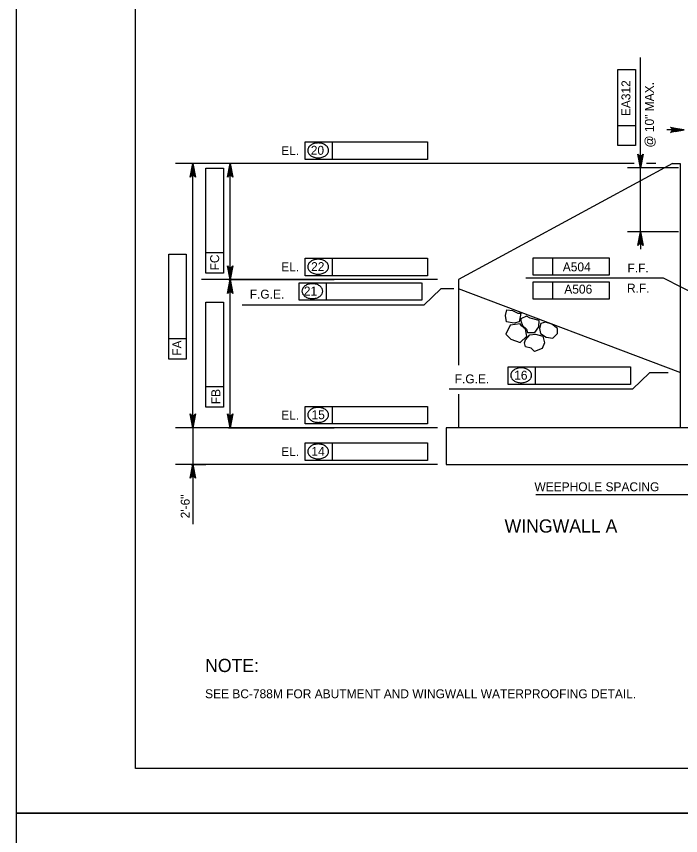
# Model space of a CAD drawing. Extents: x 638340 to 640242, y 295465 to 298435.
# Drawn here: x 638435.5 to 638658.4, y 297834 to 298109 of the extents above; entities that cross this region are included whole.
import ezdxf

# ---------------------------------------------------------------- set-up
doc = ezdxf.new("R2010")
doc.units = 0
for name, color, linetype in [('1', 7, 'Continuous'), ('2', 7, 'Continuous'), ('3', 7, 'Continuous'), ('4', 7, 'Continuous'), ('Level 10', 7, 'Continuous'), ('Level 3', 7, 'Continuous'), ('Level 4', 7, 'Continuous'), ('PLT-BNDY', 7, 'Continuous')]:
    doc.layers.add(name, color=color, linetype=linetype)

# ---------------------------------------------------------------- blocks, each defined once
blk = doc.blocks.new('ROCK')
at = {"layer": '4'}
for points in [[(2.36725, 1.088), (2.2065, 0.82625), (2.378625, 0.506625), (2.66975, 0.3095), (3.128875, 0.403375), (3.48475, 0.6775), (3.4915, 1.123375), (3.25625, 1.36725), (2.783625, 1.308375)], [(1.10175, -0.02725), (1.4015, -0.159125), (1.78825, -0.148875), (1.980875, -0.266), (2.343375, 0.09475), (2.27875, 0.5505), (1.969375, 0.883), (1.4225, 0.553625), (1.152875, 0.479), (1.0105, 0.082)], [(0.74675, 0.359875), (0.882, 0.16), (1.072875, -0.144), (0.892, -0.457375), (0.448125, -0.758625), (0.1, -0.49325), (-0.095, -0.146375), (0.202875, 0.1025), (0.579125, 0.219875)], [(2.231375, -0.71725), (2.2025, -0.266375), (2.45475, 0.037125), (2.9085, 0.28875), (3.2995, 0.047625), (3.46875, -0.344), (3.231625, -0.855), (2.92, -0.860375), (2.5765, -1.054625), (2.340375, -0.904375)], [(1.2085, -0.192875), (0.778375, -0.737625), (1.008375, -1.391375), (1.48725, -1.396875), (2.09825, -1.106625), (2.133375, -0.486375), (1.723125, -0.203375), (1.37425, -0.239875)]]:
    blk.add_lwpolyline(points, close=True, dxfattribs=at)
blk = doc.blocks.new('V')
at = {"layer": '1'}
blk.add_line((0, 0), (0, 0), dxfattribs=at)

msp = doc.modelspace()

# ---------------------------------------------------------------- linework, layer by layer
at = {"layer": '2'}
for p, q in [((638475.46, 297856.46), (638475.46, 298420.46)), ((639261.46, 297856.46), (638475.46, 297856.46))]:
    msp.add_line(p, q, dxfattribs=at)
at = {"layer": 'Level 10'}
for p, q in [((638655.6, 298059.67), (638583.82, 298020.62)), ((638655.6, 298059.67), (638658.26, 298059.67)), ((638658.26, 298059.67), (638658.26, 297970.89)), ((638583.82, 298020.62), (638583.82, 297991.94)), ((638658.48, 297989.3), (638583.82, 298017.55)), ((638583.82, 297982.19), (638583.82, 297970.89)), ((638579.73, 297970.89), (638579.73, 297958.61)), ((638740.63, 297970.89), (638579.73, 297970.89)), ((638579.73, 297958.61), (638960.22, 297958.61))]:
    msp.add_line(p, q, dxfattribs=at)
at = {"layer": 'Level 3'}
for p, q in [((638644.93, 298064.03), (638644.93, 298095.19)), ((638637.34, 298065.7), (638637.34, 298091.19)), ((638637.34, 298091.19), (638643.23, 298091.19)), ((638643.23, 298091.19), (638643.23, 298065.7)), ((638643.23, 298072.28), (638637.34, 298072.28)), ((638659.61, 298070.9), (638653.73, 298070.9)), ((638532.35, 298066.84), (638541.5, 298066.84)), ((638532.35, 298060.95), (638532.35, 298066.84)), ((638541.5, 298060.95), (638541.5, 298066.84)), ((638541.5, 298066.84), (638573.48, 298066.84)), ((638573.48, 298066.84), (638573.48, 298060.95)), ((638643.23, 298065.7), (638637.34, 298065.7)), ((638644.93, 298061.08), (638644.93, 298064.03)), ((638573.48, 298060.95), (638532.35, 298060.95)), ((638642.74, 298059.67), (638488.89, 298059.67)), ((638494.99, 298059.67), (638490.23, 298059.67)), ((638502.18, 298059.67), (638490.23, 298059.67)), ((638494.65, 297970.89), (638494.65, 298059.67)), ((638542.23, 298059.67), (638502.76, 298059.67)), ((638507.18, 298020.62), (638507.18, 298059.67)), ((638657.72, 298058.13), (638640.51, 298058.13)), ((638644.93, 298036.7), (638644.93, 298058.13)), ((638650.09, 298059.67), (638646.98, 298059.67)), ((638499.08, 298058.05), (638504.98, 298058.05)), ((638499.08, 298029.65), (638499.08, 298058.05)), ((638504.98, 298058.05), (638504.98, 298022.82)), ((638657.72, 298036.7), (638640.51, 298036.7)), ((638644.93, 298033.75), (638644.93, 298030.81)), ((638486.6, 298029.17), (638492.49, 298029.17)), ((638486.6, 298000.77), (638486.6, 298029.17)), ((638492.49, 298029.17), (638492.49, 297993.94)), ((638499.08, 298022.82), (638499.08, 298029.65)), ((638504.98, 298029.65), (638499.08, 298029.65)), ((638608.93, 298027.99), (638634.42, 298027.99)), ((638608.93, 298022.09), (638608.93, 298027.99)), ((638615.51, 298022.09), (638615.51, 298027.99)), ((638634.42, 298027.99), (638634.42, 298022.09)), ((638532.35, 298027.79), (638541.5, 298027.79)), ((638532.35, 298021.9), (638532.35, 298027.79)), ((638541.5, 298021.9), (638541.5, 298027.79)), ((638541.5, 298027.79), (638573.48, 298027.79)), ((638573.48, 298027.79), (638573.48, 298021.9)), ((638504.98, 298022.82), (638499.08, 298022.82)), ((638576.74, 298020.62), (638497.59, 298020.62)), ((638542.23, 298020.62), (638502.76, 298020.62)), ((638548.62, 298020.62), (638502.76, 298020.62)), ((638506.6, 298020.62), (638542.05, 298020.62)), ((638507.18, 297970.89), (638507.18, 298020.62)), ((638530.41, 298013.7), (638530.41, 298019.59)), ((638530.41, 298019.59), (638539.58, 298019.59)), ((638573.48, 298021.9), (638532.35, 298021.9)), ((638539.57, 298013.7), (638539.57, 298019.59)), ((638539.57, 298019.59), (638571.37, 298019.59)), ((638571.55, 298019.59), (638571.55, 298013.7)), ((638606.39, 298021.22), (638652.48, 298021.22)), ((638634.42, 298022.09), (638608.93, 298022.09)), ((638608.93, 298014.03), (638608.93, 298019.92)), ((638608.93, 298019.92), (638634.42, 298019.92)), ((638615.51, 298014.03), (638615.51, 298019.92)), ((638634.42, 298019.92), (638634.42, 298014.03)), ((638652.48, 298021.22), (638674.89, 298009.76)), ((638577.85, 298017.55), (638572.15, 298012.05)), ((638499.08, 298013.01), (638504.98, 298013.01)), ((638499.08, 297984.6), (638499.08, 298013.01)), ((638504.98, 298013.01), (638504.98, 297977.77)), ((638572.15, 298012.05), (638511.24, 298012.05)), ((638571.55, 298013.7), (638530.41, 298013.7)), ((638634.42, 298014.03), (638608.93, 298014.03)), ((638486.6, 297993.94), (638486.6, 298000.77)), ((638492.49, 298000.77), (638486.6, 298000.77)), ((638492.49, 297993.94), (638486.6, 297993.94)), ((638600.48, 297991.35), (638609.64, 297991.35)), ((638600.48, 297985.45), (638600.48, 297991.35)), ((638609.64, 297985.45), (638609.64, 297991.35)), ((638609.64, 297991.35), (638641.61, 297991.35)), ((638641.61, 297991.35), (638641.61, 297985.45)), ((638647.91, 297989.3), (638642.21, 297983.81)), ((638654.16, 297989.3), (638647.91, 297989.3)), ((638499.08, 297977.77), (638499.08, 297984.6)), ((638504.98, 297984.6), (638499.08, 297984.6)), ((638641.61, 297985.45), (638600.48, 297985.45)), ((638642.21, 297983.81), (638580.65, 297983.81)), ((638504.98, 297977.77), (638499.08, 297977.77)), ((638532.35, 297978.06), (638541.5, 297978.06)), ((638532.35, 297972.16), (638532.35, 297978.06)), ((638541.5, 297972.16), (638541.5, 297978.06)), ((638541.5, 297978.06), (638573.48, 297978.06)), ((638573.48, 297978.06), (638573.48, 297972.16)), ((638576.74, 297970.89), (638488.89, 297970.89)), ((638494.99, 297970.89), (638490.23, 297970.89)), ((638502.18, 297970.89), (638490.23, 297970.89)), ((638494.65, 297970.89), (638494.65, 297958.61)), ((638548.62, 297970.89), (638502.76, 297970.89)), ((638506.6, 297970.89), (638542.05, 297970.89)), ((638573.48, 297972.16), (638532.35, 297972.16)), ((638532.35, 297965.78), (638541.5, 297965.78)), ((638532.35, 297959.89), (638532.35, 297965.78)), ((638541.5, 297959.89), (638541.5, 297965.78)), ((638541.5, 297965.78), (638573.48, 297965.78)), ((638573.48, 297965.78), (638573.48, 297959.89)), ((638573.48, 297959.89), (638532.35, 297959.89)), ((638576.74, 297958.61), (638488.89, 297958.61)), ((638494.06, 297958.61), (638499.07, 297958.61)), ((638494.65, 297958.61), (638494.65, 297938.57)), ((638890.47, 297948.39), (638609.81, 297948.39))]:
    msp.add_line(p, q, dxfattribs=at)
for points in [[(638659.61, 298070.9), (638654.96, 298070.03), (638655.32, 298070.28), (638655.5, 298070.59), (638655.56, 298070.9), (638655.5, 298071.21), (638655.32, 298071.53), (638654.96, 298071.77), (638659.61, 298070.9), (638655.32, 298071.53), (638655.5, 298071.21), (638659.61, 298070.9), (638655.56, 298070.9), (638655.5, 298070.59), (638659.61, 298070.9), (638655.32, 298070.28)], [(638644.93, 298058.13), (638644.06, 298062.79), (638644.31, 298062.43), (638644.62, 298062.24), (638644.93, 298062.19), (638645.24, 298062.24), (638645.56, 298062.43), (638645.8, 298062.79), (638644.93, 298058.13), (638645.56, 298062.43), (638645.24, 298062.24), (638644.93, 298058.13), (638644.93, 298062.19), (638644.62, 298062.24), (638644.93, 298058.13), (638644.31, 298062.43)], [(638494.65, 298059.67), (638495.52, 298055.02), (638495.28, 298055.37), (638494.97, 298055.56), (638494.65, 298055.61), (638494.34, 298055.56), (638494.03, 298055.37), (638493.78, 298055.02), (638494.65, 298059.67), (638494.03, 298055.37), (638494.34, 298055.56), (638494.65, 298059.67), (638494.65, 298055.61), (638494.97, 298055.56), (638494.65, 298059.67), (638495.28, 298055.37)], [(638507.18, 298059.67), (638508.05, 298055.02), (638507.8, 298055.37), (638507.49, 298055.56), (638507.18, 298055.61), (638506.87, 298055.56), (638506.55, 298055.37), (638506.31, 298055.02), (638507.18, 298059.67), (638506.55, 298055.37), (638506.87, 298055.56), (638507.18, 298059.67), (638507.18, 298055.61), (638507.49, 298055.56), (638507.18, 298059.67), (638507.8, 298055.37)], [(638644.93, 298036.7), (638645.8, 298032.05), (638645.56, 298032.41), (638645.24, 298032.59), (638644.93, 298032.64), (638644.62, 298032.59), (638644.31, 298032.41), (638644.06, 298032.05), (638644.93, 298036.7), (638644.31, 298032.41), (638644.62, 298032.59), (638644.93, 298036.7), (638644.93, 298032.64), (638645.24, 298032.59), (638644.93, 298036.7), (638645.56, 298032.41)], [(638507.18, 298020.62), (638506.31, 298025.27), (638506.55, 298024.91), (638506.87, 298024.73), (638507.18, 298024.67), (638507.49, 298024.73), (638507.8, 298024.91), (638508.05, 298025.27), (638507.18, 298020.62), (638507.8, 298024.91), (638507.49, 298024.73), (638507.18, 298020.62), (638507.18, 298024.67), (638506.87, 298024.73), (638507.18, 298020.62), (638506.55, 298024.91)], [(638507.18, 298020.62), (638508.05, 298015.97), (638507.8, 298016.32), (638507.49, 298016.51), (638507.18, 298016.56), (638506.87, 298016.51), (638506.55, 298016.32), (638506.31, 298015.97), (638507.18, 298020.62), (638506.55, 298016.32), (638506.87, 298016.51), (638507.18, 298020.62), (638507.18, 298016.56), (638507.49, 298016.51), (638507.18, 298020.62), (638507.8, 298016.32)], [(638494.65, 297970.89), (638493.78, 297975.54), (638494.03, 297975.18), (638494.34, 297974.99), (638494.65, 297974.94), (638494.97, 297974.99), (638495.28, 297975.18), (638495.52, 297975.54), (638494.65, 297970.89), (638495.28, 297975.18), (638494.97, 297974.99), (638494.65, 297970.89), (638494.65, 297974.94), (638494.34, 297974.99), (638494.65, 297970.89), (638494.03, 297975.18)], [(638507.18, 297970.89), (638506.31, 297975.54), (638506.55, 297975.18), (638506.87, 297974.99), (638507.18, 297974.94), (638507.49, 297974.99), (638507.8, 297975.18), (638508.05, 297975.54), (638507.18, 297970.89), (638507.8, 297975.18), (638507.49, 297974.99), (638507.18, 297970.89), (638507.18, 297974.94), (638506.87, 297974.99), (638507.18, 297970.89), (638506.55, 297975.18)], [(638494.65, 297958.61), (638495.52, 297953.96), (638495.28, 297954.31), (638494.97, 297954.5), (638494.65, 297954.55), (638494.34, 297954.5), (638494.03, 297954.31), (638493.78, 297953.96), (638494.65, 297958.61), (638494.03, 297954.31), (638494.34, 297954.5), (638494.65, 297958.61), (638494.65, 297954.55), (638494.97, 297954.5), (638494.65, 297958.61), (638495.28, 297954.31)]]:
    msp.add_lwpolyline(points, dxfattribs=at)
for points in [[(638656.68, 298071.39), (638656.68, 298070.41), (638659.62, 298070.9)], [(638644.44, 298061.08), (638645.42, 298061.08), (638644.93, 298058.13)], [(638494.16, 298056.72), (638495.14, 298056.72), (638494.65, 298059.67)], [(638506.69, 298056.72), (638507.67, 298056.72), (638507.18, 298059.67)], [(638644.44, 298033.75), (638645.42, 298033.75), (638644.93, 298036.7)], [(638506.69, 298023.57), (638507.67, 298023.57), (638507.18, 298020.62)], [(638506.69, 298017.67), (638507.67, 298017.67), (638507.18, 298020.62)], [(638494.16, 297973.83), (638495.14, 297973.83), (638494.65, 297970.89)], [(638506.69, 297973.83), (638507.67, 297973.83), (638507.18, 297970.89)], [(638494.16, 297955.66), (638495.14, 297955.66), (638494.65, 297958.61)]]:
    msp.add_lwpolyline(points, close=True, dxfattribs=at)
for centre, radius, start, end in [((638536.72, 298061.64), 4.86, 90, 106.5358), ((638536.72, 298061.64), 4.86, 73.4642, 90), ((638535.04, 298064), 1.82, 149.9767, 180), ((638535.04, 298064), 1.82, 180, 210.0233), ((638535.85, 298063.54), 2.75, 125.6316, 149.9767), ((638536.37, 298062.8), 3.65, 106.5358, 125.6316), ((638537.06, 298062.8), 3.65, 54.3684, 73.4642), ((638537.59, 298063.54), 2.75, 30.0233, 54.3684), ((638538.39, 298064), 1.82, 0, 30.0233), ((638538.39, 298064), 1.82, 329.9767, 0), ((638535.85, 298064.47), 2.75, 210.0233, 234.3684), ((638536.37, 298065.2), 3.65, 234.3684, 253.4642), ((638536.72, 298066.36), 4.86, 253.4642, 270), ((638536.72, 298066.36), 4.86, 270, 286.5358), ((638537.06, 298065.2), 3.65, 286.5358, 305.6316), ((638537.59, 298064.47), 2.75, 305.6316, 329.9767), ((638535.04, 298024.95), 1.82, 149.9767, 180), ((638535.85, 298024.49), 2.75, 125.6316, 149.9767), ((638536.37, 298023.75), 3.65, 106.5358, 125.6316), ((638536.72, 298022.6), 4.86, 90, 106.5358), ((638536.72, 298022.6), 4.86, 73.4642, 90), ((638537.06, 298023.75), 3.65, 54.3684, 73.4642), ((638537.59, 298024.49), 2.75, 30.0233, 54.3684), ((638538.39, 298024.95), 1.82, 0, 30.0233), ((638535.04, 298024.95), 1.82, 180, 210.0233), ((638535.85, 298025.42), 2.75, 210.0233, 234.3684), ((638536.37, 298026.15), 3.65, 234.3684, 253.4642), ((638536.72, 298027.31), 4.86, 253.4642, 270), ((638536.72, 298027.31), 4.86, 270, 286.5358), ((638537.06, 298026.15), 3.65, 286.5358, 305.6316), ((638537.59, 298025.42), 2.75, 305.6316, 329.9767), ((638538.39, 298024.95), 1.82, 329.9767, 0), ((638533.11, 298016.75), 1.82, 149.9767, 180), ((638533.91, 298016.28), 2.75, 125.6316, 149.9767), ((638534.44, 298015.55), 3.65, 106.5358, 125.6316), ((638534.78, 298014.39), 4.86, 90, 106.5358), ((638534.78, 298014.39), 4.86, 73.4642, 90), ((638535.13, 298015.55), 3.65, 54.3684, 73.4642), ((638535.65, 298016.28), 2.75, 30.0233, 54.3684), ((638536.46, 298016.75), 1.82, 0, 30.0233), ((638533.11, 298016.75), 1.82, 180, 210.0233), ((638533.91, 298017.21), 2.75, 210.0233, 234.3684), ((638534.44, 298017.95), 3.65, 234.3684, 253.4642), ((638534.78, 298019.1), 4.86, 253.4642, 270), ((638534.78, 298019.1), 4.86, 270, 286.5358), ((638535.13, 298017.95), 3.65, 286.5358, 305.6316), ((638535.65, 298017.21), 2.75, 305.6316, 329.9767), ((638536.46, 298016.75), 1.82, 329.9767, 0), ((638603.18, 297988.51), 1.82, 149.9767, 180), ((638603.98, 297988.04), 2.75, 125.6316, 149.9767), ((638604.51, 297987.31), 3.65, 106.5358, 125.6316), ((638604.85, 297986.15), 4.86, 90, 106.5358), ((638604.85, 297986.15), 4.86, 73.4642, 90), ((638605.19, 297987.31), 3.65, 54.3684, 73.4642), ((638605.72, 297988.04), 2.75, 30.0233, 54.3684), ((638606.52, 297988.51), 1.82, 0, 30.0233), ((638603.18, 297988.51), 1.82, 180, 210.0233), ((638603.98, 297988.97), 2.75, 210.0233, 234.3684), ((638604.51, 297989.7), 3.65, 234.3684, 253.4642), ((638605.19, 297989.7), 3.65, 286.5358, 305.6316), ((638605.72, 297988.97), 2.75, 305.6316, 329.9767), ((638606.52, 297988.51), 1.82, 329.9767, 0), ((638604.85, 297990.86), 4.86, 253.4642, 270), ((638604.85, 297990.86), 4.86, 270, 286.5358), ((638535.04, 297975.22), 1.82, 149.9767, 180), ((638535.85, 297974.75), 2.75, 125.6316, 149.9767), ((638536.37, 297974.02), 3.65, 106.5358, 125.6316), ((638536.72, 297972.86), 4.86, 90, 106.5358), ((638536.72, 297972.86), 4.86, 73.4642, 90), ((638537.06, 297974.02), 3.65, 54.3684, 73.4642), ((638537.59, 297974.75), 2.75, 30.0233, 54.3684), ((638538.39, 297975.22), 1.82, 0, 30.0233), ((638535.04, 297975.22), 1.82, 180, 210.0233), ((638535.85, 297975.68), 2.75, 210.0233, 234.3684), ((638536.37, 297976.42), 3.65, 234.3684, 253.4642), ((638536.72, 297977.57), 4.86, 253.4642, 270), ((638536.72, 297977.57), 4.86, 270, 286.5358), ((638537.06, 297976.42), 3.65, 286.5358, 305.6316), ((638537.59, 297975.68), 2.75, 305.6316, 329.9767), ((638538.39, 297975.22), 1.82, 329.9767, 0), ((638535.85, 297962.47), 2.75, 125.6316, 149.9767), ((638536.37, 297961.74), 3.65, 106.5358, 125.6316), ((638536.72, 297960.58), 4.86, 90, 106.5358), ((638536.72, 297960.58), 4.86, 73.4642, 90), ((638537.06, 297961.74), 3.65, 54.3684, 73.4642), ((638537.59, 297962.47), 2.75, 30.0233, 54.3684), ((638535.04, 297962.94), 1.82, 149.9767, 180), ((638535.04, 297962.94), 1.82, 180, 210.0233), ((638535.85, 297963.4), 2.75, 210.0233, 234.3684), ((638537.59, 297963.4), 2.75, 305.6316, 329.9767), ((638538.39, 297962.94), 1.82, 0, 30.0233), ((638538.39, 297962.94), 1.82, 329.9767, 0), ((638536.37, 297964.14), 3.65, 234.3684, 253.4642), ((638536.72, 297965.29), 4.86, 253.4642, 270), ((638536.72, 297965.29), 4.86, 270, 286.5358), ((638537.06, 297964.14), 3.65, 286.5358, 305.6316)]:
    msp.add_arc(centre, radius, start, end, dxfattribs=at)
at = {"layer": 'Level 4'}
msp.add_line((638582.29, 298017.55), (638577.85, 298017.55), dxfattribs=at)
at = {"layer": 'PLT-BNDY'}
for points in [[(638435.46, 298435.46), (639276.46, 298435.46), (639276.46, 297841.46), (638435.46, 297841.46)], [(638435.46, 297841.46), (639276.46, 297841.46), (639276.46, 297247.46), (638435.46, 297247.46)]]:
    msp.add_lwpolyline(points, close=True, dxfattribs=at)

# ---------------------------------------------------------------- block references
at = {"layer": 'Level 3', "xscale": 0.7859001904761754, "yscale": 0.7859001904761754}
for p in [(638555.62, 298027.87), (638555.47, 298019.59)]:
    msp.add_blockref('V', p, dxfattribs=at)
at = {"layer": 'Level 3', "xscale": 4.911876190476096, "yscale": 4.9118761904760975, "rotation": -44.50373329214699}
msp.add_blockref('ROCK', (638600.94, 298010.64), dxfattribs=at)

# ---------------------------------------------------------------- texts
at = {"layer": '2'}
msp.add_text('SEE BC-788M FOR ABUTMENT AND WINGWALL WATERPROOFING DETAIL.', height=3.0001, dxfattribs=at).set_placement((638498.79, 297880.08))
at = {"layer": '3'}
msp.add_text('WINGWALL A', height=4.429, dxfattribs=at).set_placement((638599.3, 297935.7))
at = {"layer": '4'}
msp.add_text('NOTE:', height=4.429, dxfattribs=at).set_placement((638498.79, 297888.88))
at = {"layer": 'Level 3'}
for s, p in [('EA312', (638641.53, 298075.52)), ('@ 10" MAX.', (638649.4, 298064.96)), ('FC', (638503.5, 298023.71)), ('FA', (638490.84, 297995.07)), ('FB', (638503.89, 297978.79)), ('2\'-6"', (638493.61, 297940.48))]:
    msp.add_text(s, height=3, rotation=90, dxfattribs=at).set_placement(p)
for s, height, p in [('EL.', 3, (638524.34, 298062.42)), ('20', 3, (638534.25, 298062.54)), ('EL.', 3, (638524.34, 298023.38)), ('22', 3, (638534.36, 298023.49)), ('A504', 3, (638618.83, 298023.4)), ('F.F.', 3, (638640.54, 298023.02)), ('F.G.E.', 3, (638513.77, 298014.26)), ('21', 3, (638531.91, 298015.29)), ('A506', 3, (638619.34, 298015.93)), ('R.F.', 3, (638640.37, 298016.28)), ('16', 3, (638602.52, 297987.04)), ('F.G.E.', 3, (638582.56, 297985.79)), ('EL.', 3, (638524.34, 297973.64)), ('15', 3, (638534.5, 297973.76)), ('EL.', 3, (638524.34, 297961.36)), ('14', 3, (638534.47, 297961.48)), ('WEEPHOLE SPACING', 3.0001, (638609.32, 297949.58))]:
    msp.add_text(s, height=height, dxfattribs=at).set_placement(p)

doc.saveas('drawing.dxf')
